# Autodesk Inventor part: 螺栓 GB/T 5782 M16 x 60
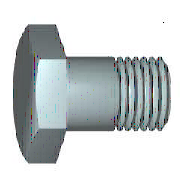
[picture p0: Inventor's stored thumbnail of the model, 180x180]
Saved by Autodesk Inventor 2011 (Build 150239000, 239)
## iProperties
Created: 2010-02
Part Number: 螺栓 GB/T 5782 M16 x 60
Material: 低炭钢
Description: 六角头螺栓
Document SubType Name: Modeling
Standard: GB/T 5782-2000
Designer: Administrator
Standard Revision: 2000
Standards Organization: GB
Language: zh-CN
Size Designation: M16x60
Categories: <MemberInstance><Categories><Category DisplayName="紧固件" InternalName="e4da775c-781d-43d5-af7c-5136215cf5a6" Mnemonic="FSTN"><Category DisplayName="螺栓" InternalN
Density: 1 g/cm^3
IsCustomPart: 1
Author: Administrator
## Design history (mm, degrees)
workplane "Work Plane1"
feature "Thread" dims "d15" = 38 (= GEL), "d16" = 0
sketch "Sketch1"
  geometry: L1 (0, 11)-(0, 8); L2 (22, 8)-(60, 8); L3 (60, 8)-(60, 0); L4 (60, 0)-(-0.5, 0); L5 (-12.6, 0)-(72.1, 0) reference; L6 (-0.5, 0)-(-0.5, 11); L7 (-0.5, 11)-(0, 11); L8 (22, 8)-(20.773, 8); L9 (20.773, 8)-(0, 8); L10 (0, -2.2)-(0, 13.2) reference
  constraints: 16 end point, 2 collinear, 2 perpendicular, 1 parallel
  dimensions: "d0" = 60 distance between parallel lines of L3 L1 (= NLG); "d1" = 38 distance from line of L2.start L3 (= GEL); "d2" = 16 diameter of L2 L4 (= GD); "d9" = 0.5001 distance between parallel lines of L6 L1 (computed from SD); "d10" = 22 diameter of L7 L4 (= SD2); "d13" = 1.227 distance of L2.start L8.end (computed from GAL); "d14" = 16 diameter of L9 L4 (= BDM)
revolve "Body" sketch "Sketch1" stored, may be unused: angle "d12" = 90 deg
sketch "Sketch2"
  geometry: L1 (0, 13.856)-(12, 6.928); L2 (12, 6.928)-(12, -6.928); L3 (12, -6.928)-(0, -13.856); L4 (0, -13.856)-(-12, -6.928); L5 (-12, -6.928)-(-12, 6.928); L6 (-12, 6.928)-(0, 13.856); 2 further points
  constraints: 12 end point, 1 coincident, 1 vertical, 11 other
  dimensions: "d11" = 24 distance between parallel lines of L5 L2 (= SW)
extrude "Head" join sketch "Sketch2" distance "d3" = 9.5 (= KOH - SD); taper "d4" = 0 deg
sketch "Sketch4"
  geometry: L1 (-10, 12)-(-10, 13.856); L2 (-10, 13.856)-(-8.928, 13.856); L3 (-8.928, 13.856)-(-10, 12); L4 (-11.9, 0)-(1.4, 0) reference; L5 (-0.5, 13.856)-(-10, 13.856) reference; L6 (-10, 6.928)-(-10, 13.856) reference
  constraints: 6 end point, 2 collinear, 1 perpendicular, 1 vertical
  dimensions: "d5" = 30 deg angle of L3 L1 (= ANG1); "d19" = 24 diameter of L1.start L4 (= SW0)
revolve "Chamfer1" stored, may be unused: angle "d21" = 90 deg
chamfer "Chamfer2" distance "d6" = 1.2269 (= -0.5 x SPD + 0.5 x GD); stored, may be unused: second distance "d7" = 1.227 (computed from GUL), angle "d55" = 45 deg
body "Solid1"
other parameters: "NLG" = 60 [user parameter; used in 1 equation term], "GD" = 16 (= NND) [user parameter; used in 2 equation terms], "BDM" = 16 (= NND) [user parameter; used in 1 equation term], "KOH" = 10 [user parameter; used in 1 equation term], "GEL" = 38 [user parameter; used in 2 equation terms], "SW" = 24 [user parameter; used in 3 equation terms], "SW0" = 24 (= SW) [user parameter; used in 1 equation term], "SPD" = 13.5462 (= NND - 1.2269 x PTC) [user parameter; used in 1 equation term], "SD2" = 22 (= SDH) [user parameter; used in 1 equation term], "SD" = 0.5 (= WFT) [user parameter; used in 2 equation terms], "ANG1" = 30 deg [user parameter; used in 1 equation term], "GAL" = 1.2269 (= 0.61345 x PTC) [user parameter; used in 1 equation term], "GUL" = 1.2269 (= 0.61345 x PTC) [user parameter; used in 1 equation term], "d8" = 0, "RR" = 0.6 [user parameter], "d57" = 0, "d58" = 0, "TPU" = 5 (computed from PTC) [user parameter], "WFT" = 0.5 [user parameter; used in 1 equation term], "GD1" = 13.5462 (= THREADDIA - 1.2269 x PTC) [user parameter], "THREADDIA" = 16 [user parameter; used in 1 equation term], "SDH" = 22 [user parameter; used in 1 equation term], "TOA" = 30 deg [user parameter], "FAWI" = 45 deg [user parameter], "PTC" = 2 [user parameter; used in 5 equation terms], "NND" = 16 [user parameter; used in 3 equation terms], "E0" = 27.72 (= 1.155 x SW) [user parameter]
